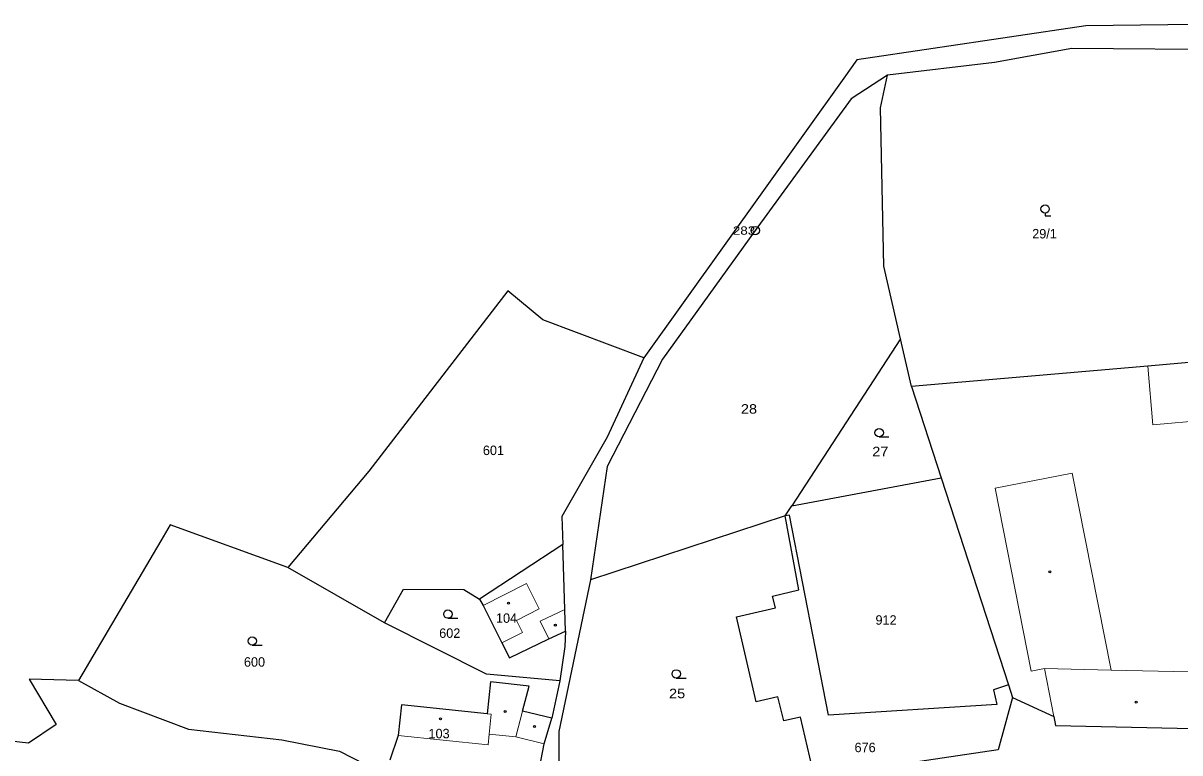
# Model space of a CAD drawing. Extents: x -754445 to -751443, y -1030748 to -1028224.
# Drawn here: x -752770.5 to -752562.9, y -1029122.6 to -1028991.5 of the extents above; entities that cross this region are included whole.
import ezdxf
from ezdxf.enums import TextEntityAlignment as Align

# ---------------------------------------------------------------- set-up
doc = ezdxf.new("R2010")
doc.units = 0
doc.header["$LTSCALE"] = 0.68
for name, color, linetype, lineweight in [('1', 7, 'Continuous', 25), ('3', 7, 'Continuous', 25), ('4', 7, 'Continuous', 13), ('5', 7, 'Continuous', 25), ('8', 7, 'Continuous', 25)]:
    doc.layers.add(name, color=color, linetype=linetype, lineweight=lineweight)
doc.layers.add('2', color=7, linetype='Continuous')

msp = doc.modelspace()

# ---------------------------------------------------------------- linework, layer by layer
at = {"layer": '1'}
for p, q in [((-752613, -1029048.21), (-752632.52, -1029078.19)), ((-752611.04, -1029056.77), (-752613, -1029048.21)), ((-752632.52, -1029078.19), (-752605.72, -1029073.17)), ((-752633.71, -1029080.02), (-752632.52, -1029078.19)), ((-752633.71, -1029080.02), (-752668.67, -1029091.51)), ((-752744.1, -1029081.61), (-752745.79, -1029084.48)), ((-752722.99, -1029089.28), (-752744.1, -1029081.61)), ((-752745.79, -1029084.48), (-752760.57, -1029109.57)), ((-752673.62, -1029085.13), (-752688.58, -1029094.94)), ((-752760.57, -1029109.57), (-752769.41, -1029109.33))]:
    msp.add_line(p, q, dxfattribs=at)
for points in [[(-752540.55, -1028991.5), (-752579.74, -1028992), (-752620.85, -1028998.11)], [(-752552.44, -1028996.32), (-752582.25, -1028996.08), (-752596.14, -1028998.6), (-752615.36, -1029000.87)], [(-752620.85, -1028998.11), (-752623.17, -1029001.36), (-752659.08, -1029051.61)], [(-752615.36, -1029000.87), (-752621.87, -1029005.11), (-752639.1, -1029028.76), (-752655.76, -1029051.88), (-752665.69, -1029071.12), (-752668.67, -1029091.51)], [(-752613, -1029048.21), (-752615.99, -1029035.13), (-752616.6, -1029006.72), (-752615.36, -1029000.87)], [(-752659.08, -1029051.61), (-752677.22, -1029044.79), (-752683.53, -1029039.57), (-752708.48, -1029071.96), (-752722.99, -1029089.28)], [(-752659.08, -1029051.61), (-752665.69, -1029065.88), (-752673.79, -1029080.14), (-752673.62, -1029085.13)], [(-752554.48, -1029051.86), (-752568.65, -1029053.09), (-752611.04, -1029056.77)], [(-752611.04, -1029056.77), (-752605.72, -1029073.17), (-752593.66, -1029110.35), (-752592.92, -1029112.62)], [(-752628.44, -1029126.95), (-752630.95, -1029116.14), (-752633.97, -1029116.84), (-752635.02, -1029112.5), (-752638.92, -1029113.4), (-752642.46, -1029098.12), (-752635.49, -1029096.51), (-752635.98, -1029094.41), (-752631.26, -1029093.31), (-752633.71, -1029080.02)], [(-752593.66, -1029110.35), (-752596.36, -1029111.23), (-752595.73, -1029113.9), (-752625.97, -1029115.82), (-752632.92, -1029079.87), (-752633.71, -1029080.02)], [(-752673.18, -1029100.68), (-752673.29, -1029096.79), (-752673.62, -1029085.13)], [(-752674.18, -1029109.65), (-752687.35, -1029108.46), (-752705.66, -1029099.23), (-752722.99, -1029089.28)], [(-752705.66, -1029099.23), (-752702.23, -1029093.18), (-752691.4, -1029093.22), (-752688.58, -1029094.94)], [(-752668.67, -1029091.51), (-752674.37, -1029118.71), (-752674.39, -1029136.41)], [(-752688.58, -1029094.94), (-752687.96, -1029096.11), (-752684.56, -1029102.8), (-752683.19, -1029105.5), (-752676.16, -1029102.11), (-752673.18, -1029100.68)], [(-752673.18, -1029100.68), (-752673.27, -1029103.47), (-752674.18, -1029109.65), (-752675.58, -1029116.36)], [(-752769.41, -1029109.33), (-752764.57, -1029117.45), (-752769.55, -1029120.83), (-752781.24, -1029119.49)], [(-752760.57, -1029109.57), (-752753.18, -1029113.62), (-752740.82, -1029118.28), (-752724.1, -1029120.25), (-752713.71, -1029122.28), (-752709.15, -1029124.62)], [(-752675.58, -1029116.36), (-752680.85, -1029115.08), (-752679.65, -1029110.57), (-752686.61, -1029109.83), (-752687.21, -1029115.55), (-752702.58, -1029113.93), (-752703.16, -1029119.45), (-752704.67, -1029123.9)], [(-752592.92, -1029112.62), (-752595.52, -1029122), (-752628.44, -1029126.95)], [(-752592.92, -1029112.62), (-752585.52, -1029116.03), (-752585.21, -1029117.65), (-752557.91, -1029118.23), (-752551.4, -1029118.11), (-752524.46, -1029116.95)], [(-752677.84, -1029125.32), (-752676.99, -1029120.94), (-752675.58, -1029116.36)]]:
    msp.add_lwpolyline(points, dxfattribs=at)
at = {"layer": '3'}
for p, q in [((-752616.853, -1029065.81), (-752615.103, -1029065.81)), ((-752694.253, -1029098.4), (-752692.503, -1029098.4)), ((-752729.373, -1029103.23), (-752727.623, -1029103.23)), ((-752653.273, -1029109.14), (-752651.523, -1029109.14))]:
    msp.add_line(p, q, dxfattribs=at)
msp.add_lwpolyline([(-752587.07, -1029025.632), (-752587.07, -1029026.13), (-752586.069, -1029026.13)], dxfattribs=at)
for centre in [(-752587.0693, -1029024.8809), (-752616.8529, -1029065.0598), (-752694.2529, -1029097.6498), (-752729.3729, -1029102.4798), (-752653.2729, -1029108.3898)]:
    msp.add_circle(centre, 0.75, dxfattribs=at)
at = {"layer": '4'}
for p, q in [((-752568.65, -1029053.09), (-752567.74, -1029063.65)), ((-752567.74, -1029063.65), (-752525.62, -1029060.01)), ((-752596.05, -1029075.05), (-752582.22, -1029072.32)), ((-752575.24, -1029107.69), (-752582.22, -1029072.32)), ((-752589.57, -1029107.91), (-752596.05, -1029075.05)), ((-752687.96, -1029096.11), (-752680.17, -1029092.16)), ((-752680.17, -1029092.16), (-752677.86, -1029096.71)), ((-752681.96, -1029098.8), (-752677.86, -1029096.71)), ((-752673.29, -1029096.79), (-752677.7, -1029098.91)), ((-752681.96, -1029098.8), (-752680.88, -1029100.93)), ((-752677.7, -1029098.91), (-752676.16, -1029102.11)), ((-752684.56, -1029102.8), (-752680.88, -1029100.93)), ((-752589.57, -1029107.91), (-752587.16, -1029107.44)), ((-752587.16, -1029107.44), (-752575.24, -1029107.69)), ((-752585.52, -1029116.03), (-752587.16, -1029107.44)), ((-752575.24, -1029107.69), (-752557.69, -1029108.06)), ((-752686.48, -1029115.63), (-752687.21, -1029115.55)), ((-752686.48, -1029115.63), (-752686.86, -1029119.2)), ((-752682.08, -1029119.71), (-752680.85, -1029115.08)), ((-752687.06, -1029121.15), (-752703.16, -1029119.45)), ((-752686.86, -1029119.2), (-752687.06, -1029121.15)), ((-752686.86, -1029119.2), (-752682.08, -1029119.71)), ((-752682.08, -1029119.71), (-752676.99, -1029120.94))]:
    msp.add_line(p, q, dxfattribs=at)
at = {"layer": '5'}
for centre in [(-752586.2068, -1029090.0292), (-752683.3768, -1029095.6592), (-752674.9768, -1029099.6392), (-752570.7468, -1029113.4392), (-752683.9768, -1029115.1492), (-752695.5668, -1029116.4692), (-752678.7268, -1029117.8392)]:
    msp.add_circle(centre, 0.175, dxfattribs=at)
at = {"layer": '8'}
for radius in [0.75, 0.03]:
    msp.add_circle((-752639.1, -1029028.7598), radius, dxfattribs=at)

# ---------------------------------------------------------------- texts
at = {"layer": '2'}
for s, p in [('29/1', (-752587.17, -1029030.17)), ('601', (-752686.089, -1029069.08)), ('104', (-752683.739, -1029099.21)), ('912', (-752615.619, -1029099.55)), ('602', (-752693.929, -1029101.91)), ('600', (-752728.979, -1029107.09)), ('103', (-752695.849, -1029119.95)), ('676', (-752619.379, -1029122.44))]:
    msp.add_text(s, height=1.7, dxfattribs=at).set_placement(p, align=Align.CENTER)
at = {"layer": '2', "width": 1.15}
for s, p in [('28', (-752640.22, -1029061.64)), ('27', (-752616.65, -1029069.29)), ('25', (-752653.12, -1029112.75))]:
    msp.add_text(s, height=1.7, dxfattribs=at).set_placement(p, align=Align.CENTER)
at = {"layer": '8', "width": 1.2}
msp.add_text('283', height=1.5, dxfattribs=at).set_placement((-752639.1, -1029029.51), align=Align.RIGHT)

doc.saveas('drawing.dxf')
